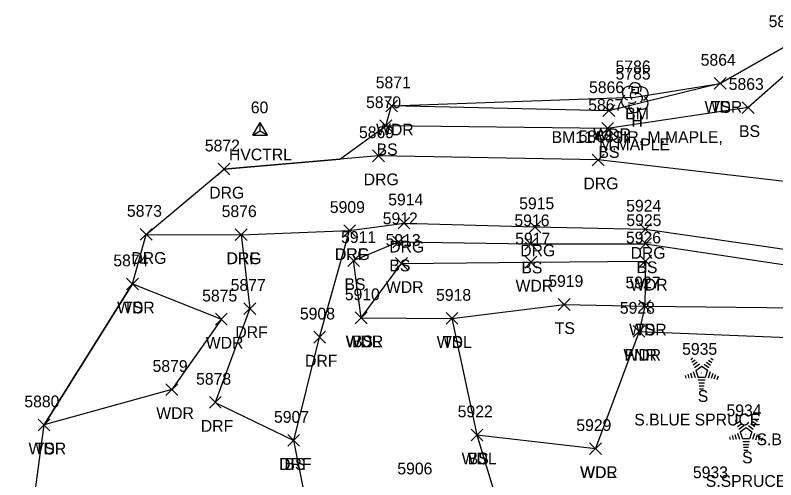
# Model space of a CAD drawing. Extents: x 1472233 to 1475777, y 540726 to 543442.
# Drawn here: x 1472262 to 1472391.2, y 541867.2 to 541946.1 of the extents above; entities that cross this region are included whole.
import ezdxf

# ---------------------------------------------------------------- set-up
doc = ezdxf.new("R2010")
doc.units = 0
for name, color, linetype in [('C_A', 7, 'Continuous'), ('C_C', 7, 'Continuous'), ('C_I', 7, 'Continuous'), ('CPBM', 7, 'Continuous'), ('CPSM', 7, 'Continuous'), ('L_A', 7, 'Continuous'), ('L_C', 7, 'Continuous'), ('L_I', 7, 'Continuous'), ('L_TIC', 7, 'Continuous'), ('LAWA', 7, 'Continuous'), ('LELB', 7, 'Continuous'), ('LFNC', 7, 'Continuous'), ('LSOGP', 7, 'Continuous'), ('LTC', 7, 'Continuous'), ('LTD', 7, 'Continuous'), ('R_A', 7, 'Continuous'), ('R_I', 7, 'Continuous'), ('R_TIC', 7, 'Continuous'), ('RDF', 7, 'Continuous'), ('RDG', 7, 'Continuous')]:
    doc.layers.add(name, color=color, linetype=linetype)

msp = doc.modelspace()

# ---------------------------------------------------------------- linework, layer by layer
at = {"layer": 'CPBM'}
for p, q in [((1472366.77, 541932.93), (1472366.77, 541933.93)), ((1472366.77, 541933.93), (1472367.77, 541933.93)), ((1472367.27, 541933.43), (1472367.27, 541933.43)), ((1472367.27, 541933.43), (1472367.27, 541933.43)), ((1472367.77, 541933.93), (1472367.77, 541932.93)), ((1472367.77, 541932.93), (1472366.77, 541932.93))]:
    msp.add_line(p, q, dxfattribs=at)
at = {"layer": 'CPSM'}
for p, q in [((1472302.37, 541925.75), (1472303.62, 541927.92)), ((1472304.87, 541925.75), (1472303.62, 541927.92)), ((1472303.62, 541926.47), (1472303.62, 541927.92)), ((1472302.37, 541925.75), (1472303.62, 541926.47)), ((1472302.37, 541925.75), (1472304.87, 541925.75)), ((1472303.62, 541926.47), (1472303.62, 541926.47)), ((1472303.62, 541926.47), (1472304.87, 541925.75))]:
    msp.add_line(p, q, dxfattribs=at)
at = {"layer": 'L_TIC'}
for points in [[(1472380.71, 541933.55), (1472382.71, 541935.55)], [(1472382.71, 541933.55), (1472380.71, 541935.55)], [(1472380.71, 541933.55), (1472382.71, 541935.55)], [(1472382.71, 541933.55), (1472380.71, 541935.55)], [(1472324.93, 541929.71), (1472326.93, 541931.71)], [(1472326.93, 541929.71), (1472324.93, 541931.71)], [(1472361.81, 541928.9), (1472363.81, 541930.9)], [(1472363.81, 541928.9), (1472361.81, 541930.9)], [(1472385.48, 541929.44), (1472387.48, 541931.44)], [(1472387.48, 541929.44), (1472385.48, 541931.44)], [(1472323.94, 541926.35), (1472325.94, 541928.35)], [(1472325.94, 541926.35), (1472323.94, 541928.35)], [(1472361.61, 541925.89), (1472363.61, 541927.89)], [(1472363.61, 541925.89), (1472361.61, 541927.89)], [(1472326.11, 541906.62), (1472328.11, 541908.62)], [(1472328.11, 541906.62), (1472326.11, 541908.62)], [(1472348.53, 541906.28), (1472350.53, 541908.28)], [(1472350.53, 541906.28), (1472348.53, 541908.28)], [(1472368.05, 541906.32), (1472370.05, 541908.32)], [(1472370.05, 541906.32), (1472368.05, 541908.32)], [(1472318.48, 541903.44), (1472320.48, 541905.44)], [(1472320.48, 541903.44), (1472318.48, 541905.44)], [(1472326.6, 541902.95), (1472328.6, 541904.95)], [(1472328.6, 541902.95), (1472326.6, 541904.95)], [(1472348.61, 541903.18), (1472350.61, 541905.18)], [(1472350.61, 541903.18), (1472348.61, 541905.18)], [(1472368.04, 541903.36), (1472370.04, 541905.36)], [(1472370.04, 541903.36), (1472368.04, 541905.36)], [(1472280.94, 541899.48), (1472282.94, 541901.48)], [(1472282.94, 541899.48), (1472280.94, 541901.48)], [(1472280.94, 541899.48), (1472282.94, 541901.48)], [(1472282.94, 541899.48), (1472280.94, 541901.48)], [(1472354.23, 541895.98), (1472356.23, 541897.98)], [(1472356.23, 541895.98), (1472354.23, 541897.98)], [(1472367.9, 541895.73), (1472369.9, 541897.73)], [(1472369.9, 541895.73), (1472367.9, 541897.73)], [(1472367.9, 541895.73), (1472369.9, 541897.73)], [(1472369.9, 541895.73), (1472367.9, 541897.73)], [(1472296.02, 541893.49), (1472298.02, 541895.49)], [(1472298.02, 541893.49), (1472296.02, 541895.49)], [(1472319.76, 541893.72), (1472321.76, 541895.72)], [(1472321.76, 541893.72), (1472319.76, 541895.72)], [(1472319.76, 541893.72), (1472321.76, 541895.72)], [(1472321.76, 541893.72), (1472319.76, 541895.72)], [(1472319.76, 541893.72), (1472321.76, 541895.72)], [(1472321.76, 541893.72), (1472319.76, 541895.72)], [(1472335.17, 541893.62), (1472337.17, 541895.62)], [(1472337.17, 541893.62), (1472335.17, 541895.62)], [(1472335.17, 541893.62), (1472337.17, 541895.62)], [(1472337.17, 541893.62), (1472335.17, 541895.62)], [(1472366.94, 541891.42), (1472368.94, 541893.42)], [(1472368.94, 541891.42), (1472366.94, 541893.42)], [(1472366.94, 541891.42), (1472368.94, 541893.42)], [(1472368.94, 541891.42), (1472366.94, 541893.42)], [(1472287.61, 541881.54), (1472289.61, 541883.54)], [(1472289.61, 541881.54), (1472287.61, 541883.54)], [(1472265.92, 541875.52), (1472267.92, 541877.52)], [(1472267.92, 541875.52), (1472265.92, 541877.52)], [(1472265.92, 541875.52), (1472267.92, 541877.52)], [(1472267.92, 541875.52), (1472265.92, 541877.52)], [(1472339.41, 541873.83), (1472341.41, 541875.83)], [(1472341.41, 541873.83), (1472339.41, 541875.83)], [(1472339.41, 541873.83), (1472341.41, 541875.83)], [(1472341.41, 541873.83), (1472339.41, 541875.83)], [(1472308.3, 541872.9), (1472310.3, 541874.9)], [(1472310.3, 541872.9), (1472308.3, 541874.9)], [(1472359.55, 541871.5), (1472361.55, 541873.5)], [(1472361.55, 541871.5), (1472359.55, 541873.5)], [(1472359.55, 541871.5), (1472361.55, 541873.5)], [(1472361.55, 541871.5), (1472359.55, 541873.5)]]:
    msp.add_lwpolyline(points, dxfattribs=at)
at = {"layer": 'LAWA'}
for points in [[(1472381.71, 541934.55), (1472362.81, 541929.9), (1472325.93, 541930.71)], [(1472320.76, 541894.72), (1472327.6, 541903.95), (1472349.61, 541904.18), (1472369.04, 541904.36), (1472368.9, 541896.73), (1472367.94, 541892.42), (1472360.55, 541872.5)], [(1472281.94, 541900.48), (1472297.02, 541894.49), (1472288.61, 541882.54), (1472266.92, 541876.52)], [(1472320.76, 541894.72), (1472336.17, 541894.62), (1472340.41, 541874.83), (1472360.55, 541872.5)]]:
    msp.add_lwpolyline(points, dxfattribs=at)
at = {"layer": 'LELB'}
for points in [[(1472393.27, 541941.1), (1472381.71, 541934.55)], [(1472396.36, 541939.17), (1472386.48, 541930.44), (1472362.61, 541926.89), (1472324.94, 541927.35)], [(1472320.76, 541894.72), (1472319.48, 541904.44), (1472327.11, 541907.62), (1472349.53, 541907.28), (1472369.05, 541907.32), (1472400.34, 541902.59), (1472412.63, 541895.66), (1472425.56, 541876.84), (1472441.12, 541840.86)], [(1472281.94, 541900.48), (1472266.92, 541876.52)], [(1472336.17, 541894.62), (1472355.23, 541896.98), (1472368.9, 541896.73), (1472400.02, 541896.36), (1472408.73, 541890.9), (1472414.63, 541871.63)], [(1472283.6, 541808.58), (1472290.39, 541830.97), (1472298.7, 541848.77), (1472310.08, 541852), (1472313.82, 541851.56), (1472309.3, 541873.9)], [(1472340.41, 541874.83), (1472344.78, 541860.43), (1472364.31, 541858.54), (1472393.01, 541845.61), (1472400.41, 541826.82), (1472401.16, 541806.06)]]:
    msp.add_lwpolyline(points, dxfattribs=at)
at = {"layer": 'LFNC'}
msp.add_lwpolyline([(1472367.94, 541892.42), (1472397.42, 541891.24), (1472408.73, 541890.9), (1472418.35, 541874.05), (1472429.29, 541846.34), (1472434.3, 541834.91), (1472432.16, 541828.28)], dxfattribs=at)
at = {"layer": 'LSOGP'}
msp.add_lwpolyline([(1472313.53, 541780.33), (1472308.58, 541803.57), (1472307.76, 541802.6), (1472300.01, 541804.6), (1472283.6, 541808.58), (1472268.24, 541812.15), (1472267.36, 541823.78), (1472262.02, 541839.94), (1472266.92, 541876.52), (1472281.94, 541900.48), (1472284.25, 541908.89), (1472297.47, 541919.99), (1472304.03, 541920.55), (1472310.58, 541921.11), (1472317.14, 541921.67), (1472324.94, 541927.35), (1472325.93, 541930.71), (1472367.22, 541932.19), (1472381.71, 541934.55), (1472393.27, 541941.1)], dxfattribs=at)
at = {"layer": 'LTC'}
for p, q in [((1472376.72, 541887.65), (1472377.07, 541887.91)), ((1472376.93, 541887.19), (1472377.45, 541887.57)), ((1472377.13, 541886.72), (1472377.84, 541887.23)), ((1472377.34, 541886.26), (1472378.22, 541886.89)), ((1472379, 541886.85), (1472379.81, 541886.26)), ((1472379.37, 541887.2), (1472380.05, 541886.7)), ((1472379.74, 541887.55), (1472380.29, 541887.15)), ((1472380.11, 541887.89), (1472380.53, 541887.59)), ((1472377.11, 541885.58), (1472377.45, 541884.56)), ((1472377.57, 541885.8), (1472378.58, 541886.54)), ((1472377.57, 541885.8), (1472377.96, 541884.61)), ((1472378.58, 541886.54), (1472379.58, 541885.81)), ((1472379.58, 541885.81), (1472379.19, 541884.61)), ((1472380.02, 541885.54), (1472379.68, 541884.5)), ((1472375.75, 541884.93), (1472375.9, 541884.46)), ((1472376.2, 541885.15), (1472376.42, 541884.5)), ((1472376.66, 541885.37), (1472376.93, 541884.53)), ((1472379.19, 541884.61), (1472377.96, 541884.61)), ((1472380.46, 541885.29), (1472380.17, 541884.4)), ((1472380.9, 541885.04), (1472380.67, 541884.31)), ((1472381.35, 541884.79), (1472381.16, 541884.21)), ((1472379.15, 541884.11), (1472378, 541884.11)), ((1472379.06, 541883.61), (1472378.08, 541883.61)), ((1472378.98, 541883.11), (1472378.15, 541883.11)), ((1472378.9, 541882.61), (1472378.22, 541882.61)), ((1472384.25, 541877.22), (1472384.6, 541877.47)), ((1472384.46, 541876.75), (1472384.99, 541877.14)), ((1472384.67, 541876.29), (1472385.37, 541876.8)), ((1472386.9, 541876.76), (1472387.58, 541876.27)), ((1472387.28, 541877.11), (1472387.82, 541876.71)), ((1472387.65, 541877.46), (1472388.07, 541877.15)), ((1472384.88, 541875.82), (1472385.76, 541876.46)), ((1472385.1, 541875.37), (1472386.11, 541876.1)), ((1472385.1, 541875.37), (1472385.49, 541874.17)), ((1472386.11, 541876.1), (1472387.11, 541875.37)), ((1472386.53, 541876.41), (1472387.34, 541875.82)), ((1472387.11, 541875.37), (1472386.72, 541874.17)), ((1472383.28, 541874.5), (1472383.43, 541874.03)), ((1472383.74, 541874.71), (1472383.95, 541874.06)), ((1472384.19, 541874.93), (1472384.46, 541874.09)), ((1472384.65, 541875.15), (1472384.98, 541874.13)), ((1472386.72, 541874.17), (1472385.49, 541874.17)), ((1472387.55, 541875.1), (1472387.21, 541874.06)), ((1472387.99, 541874.85), (1472387.7, 541873.97)), ((1472388.44, 541874.6), (1472388.2, 541873.87)), ((1472388.88, 541874.35), (1472388.69, 541873.78)), ((1472386.68, 541873.67), (1472385.54, 541873.67)), ((1472386.6, 541873.17), (1472385.61, 541873.17)), ((1472386.51, 541872.67), (1472385.68, 541872.67)), ((1472386.43, 541872.17), (1472385.75, 541872.17))]:
    msp.add_line(p, q, dxfattribs=at)
at = {"layer": 'LTD'}
msp.add_line((1472367.22, 541932.19), (1472367.22, 541932.19), dxfattribs=at)
msp.add_line((1472367.22, 541932.19), (1472367.22, 541932.19), dxfattribs=at)
msp.add_arc((1472367.26, 541933.62), 1.05, 335.5272, 180.9563, dxfattribs=at)
for centre, major_axis, ratio, start_param, end_param in [((1472366.42, 541932.86), (1.21, -0.51), 0.895232, 1.570796, 4.712389), ((1472367.01, 541932.65), (-0.208, -0.792), 0.645439, 3.141593, 6.283185), ((1472368.26, 541932.77), (-1.14, -0.48), 0.949671, 1.570796, 4.712389), ((1472366.13, 541931.48), (0.58, -1.04), 0.959034, 3.141593, 6.283185), ((1472367.72, 541932.02), (-0.5, 0.667), 0.989748, 3.141593, 6.283185), ((1472368.22, 541931.36), (-1.09, 0.79), 0.841452, 1.570796, 4.712389), ((1472367.22, 541930.69), (0.26, 1.06), 0.942809, 1.570796, 4.712389), ((1472366.76, 541931.44), (-0.625, -0.083), 0.423636, 0, 3.141593)]:
    msp.add_ellipse(centre, major_axis=major_axis, ratio=ratio, start_param=start_param, end_param=end_param, dxfattribs=at)
at = {"layer": 'R_TIC'}
for points in [[(1472322.7, 541921.24), (1472324.7, 541923.24)], [(1472324.7, 541921.24), (1472322.7, 541923.24)], [(1472360.01, 541920.55), (1472362.01, 541922.55)], [(1472362.01, 541920.55), (1472360.01, 541922.55)], [(1472296.47, 541918.99), (1472298.47, 541920.99)], [(1472298.47, 541918.99), (1472296.47, 541920.99)], [(1472327.04, 541909.82), (1472329.04, 541911.82)], [(1472329.04, 541909.82), (1472327.04, 541911.82)], [(1472317.79, 541908.54), (1472319.79, 541910.54)], [(1472319.79, 541908.54), (1472317.79, 541910.54)], [(1472317.79, 541908.54), (1472319.79, 541910.54)], [(1472319.79, 541908.54), (1472317.79, 541910.54)], [(1472349.28, 541909.17), (1472351.28, 541911.17)], [(1472351.28, 541909.17), (1472349.28, 541911.17)], [(1472368.02, 541908.76), (1472370.02, 541910.76)], [(1472370.02, 541908.76), (1472368.02, 541910.76)], [(1472283.25, 541907.89), (1472285.25, 541909.89)], [(1472285.25, 541907.89), (1472283.25, 541909.89)], [(1472299.38, 541907.84), (1472301.38, 541909.84)], [(1472301.38, 541907.84), (1472299.38, 541909.84)], [(1472299.38, 541907.84), (1472301.38, 541909.84)], [(1472301.38, 541907.84), (1472299.38, 541909.84)], [(1472300.86, 541895.3), (1472302.86, 541897.3)], [(1472302.86, 541895.3), (1472300.86, 541897.3)], [(1472312.7, 541890.44), (1472314.7, 541892.44)], [(1472314.7, 541890.44), (1472312.7, 541892.44)], [(1472294.99, 541879.36), (1472296.99, 541881.36)], [(1472296.99, 541879.36), (1472294.99, 541881.36)], [(1472308.3, 541872.9), (1472310.3, 541874.9)], [(1472310.3, 541872.9), (1472308.3, 541874.9)]]:
    msp.add_lwpolyline(points, dxfattribs=at)
at = {"layer": 'RDF'}
msp.add_lwpolyline([(1472300.38, 541908.84), (1472301.86, 541896.3), (1472295.99, 541880.36), (1472309.3, 541873.9), (1472313.7, 541891.44), (1472318.79, 541909.54)], dxfattribs=at)
at = {"layer": 'RDG'}
for points in [[(1472417.04, 541924.07), (1472412.17, 541918.8), (1472398.55, 541917.2), (1472361.01, 541921.55), (1472323.7, 541922.24), (1472297.47, 541919.99)], [(1472284.25, 541908.89), (1472300.38, 541908.84), (1472318.79, 541909.54), (1472328.04, 541910.82), (1472350.28, 541910.17), (1472369.02, 541909.76), (1472411.16, 541903.71), (1472423.64, 541895.51), (1472429.27, 541890.41)]]:
    msp.add_lwpolyline(points, dxfattribs=at)

# ---------------------------------------------------------------- texts
at = {"layer": 'C_A'}
for s, p in [('BM', (1472365.59, 541928.43)), ('HVCTRL', (1472298.31, 541921.47))]:
    msp.add_text(s, height=2, dxfattribs=at).set_placement(p)
at = {"layer": 'C_C'}
msp.add_text('BM11A=SIR, M.MAPLE,', height=2, dxfattribs=at).set_placement((1472353.1, 541924.43))
at = {"layer": 'C_I'}
for s, p in [('5786', (1472363.96, 541936.43)), ('60', (1472302.02, 541929.47))]:
    msp.add_text(s, height=2, dxfattribs=at).set_placement(p)
at = {"layer": 'L_A'}
for s, p in [('WDR', (1472379.08, 541929.55)), ('TS', (1472380.12, 541929.55)), ('H', (1472366.65, 541927.19)), ('WDR', (1472323.29, 541925.71)), ('WDR', (1472360.17, 541924.9)), ('BS', (1472384.92, 541925.44)), ('BS', (1472323.38, 541922.35)), ('BS', (1472361.06, 541921.89)), ('BS', (1472325.55, 541902.62)), ('BS', (1472347.97, 541902.28)), ('BS', (1472367.5, 541902.32)), ('BS', (1472317.92, 541899.44)), ('WDR', (1472346.98, 541899.18)), ('WDR', (1472366.4, 541899.36)), ('WDR', (1472324.96, 541898.95)), ('WDR', (1472279.31, 541895.48)), ('TS', (1472280.35, 541895.48)), ('TS', (1472353.64, 541891.98)), ('WDR', (1472366.26, 541891.73)), ('TS', (1472367.31, 541891.73)), ('WDR', (1472294.38, 541889.49)), ('WDR', (1472318.12, 541889.72)), ('WDL', (1472318.18, 541889.72)), ('BS', (1472319.2, 541889.72)), ('WDL', (1472333.59, 541889.62)), ('TS', (1472334.58, 541889.62)), ('WDR', (1472365.3, 541887.42)), ('FNR', (1472365.47, 541887.42)), ('S', (1472377.91, 541880.44)), ('WDR', (1472285.97, 541877.54)), ('WDR', (1472264.28, 541871.52)), ('TS', (1472265.33, 541871.52)), ('WDL', (1472337.82, 541869.83)), ('BS', (1472338.85, 541869.83)), ('S', (1472385.44, 541870.01)), ('BS', (1472307.74, 541868.9)), ('WDR', (1472357.92, 541867.5)), ('WDL', (1472357.97, 541867.5))]:
    msp.add_text(s, height=2, dxfattribs=at).set_placement(p)
at = {"layer": 'L_C'}
for s, p in [('M.MAPLE', (1472361.15, 541923.19)), ('S.BLUE SPRUCE', (1472367.13, 541876.44)), ('S.BLUE SPRUCE', (1472387.89, 541873.09)), ('S.SPRUCE', (1472379.27, 541866.01))]:
    msp.add_text(s, height=2, dxfattribs=at).set_placement(p)
at = {"layer": 'L_I'}
for s, p in [('5856', (1472389.95, 541944.1)), ('5864', (1472378.41, 541937.55)), ('5864', (1472378.41, 541937.55)), ('5785', (1472363.96, 541935.19)), ('5871', (1472323.23, 541933.71)), ('5866', (1472359.45, 541932.9)), ('5863', (1472383.17, 541933.44)), ('5870', (1472321.59, 541930.35)), ('5867', (1472359.31, 541929.89)), ('5912', (1472324.42, 541910.62)), ('5916', (1472346.78, 541910.28)), ('5925', (1472365.79, 541910.32)), ('5911', (1472317.35, 541907.44)), ('5913', (1472324.91, 541906.95)), ('5917', (1472346.92, 541907.18)), ('5926', (1472365.72, 541907.36)), ('5874', (1472278.68, 541903.48)), ('5874', (1472278.68, 541903.48)), ('5919', (1472352.53, 541899.98)), ('5927', (1472365.64, 541899.73)), ('5927', (1472365.64, 541899.73)), ('5910', (1472317.98, 541897.72)), ('5910', (1472317.98, 541897.72)), ('5910', (1472317.98, 541897.72)), ('5875', (1472293.76, 541897.49)), ('5918', (1472333.48, 541897.62)), ('5918', (1472333.48, 541897.62)), ('5928', (1472364.68, 541895.42)), ('5928', (1472364.68, 541895.42)), ('5935', (1472375.26, 541888.44)), ('5879', (1472285.34, 541885.54)), ('5880', (1472263.57, 541879.52)), ('5880', (1472263.57, 541879.52)), ('5922', (1472337.15, 541877.83)), ('5922', (1472337.15, 541877.83)), ('5934', (1472382.79, 541878.01)), ('5907', (1472305.96, 541876.9)), ('5929', (1472357.29, 541875.5)), ('5929', (1472357.29, 541875.5)), ('5906', (1472326.9, 541868.13)), ('5933', (1472377.09, 541867.48))]:
    msp.add_text(s, height=2, dxfattribs=at).set_placement(p)
at = {"layer": 'LTC'}
for p in [(1472378.46, 541885.55), (1472386, 541875.11)]:
    msp.add_text('.', height=1.04, rotation=270, dxfattribs=at).set_placement(p)
at = {"layer": 'R_A'}
for s, p in [('DRG', (1472321.19, 541917.24)), ('DRG', (1472358.5, 541916.55)), ('DRG', (1472294.96, 541914.99)), ('DRG', (1472325.53, 541905.82)), ('DRG', (1472316.27, 541904.54)), ('DRF', (1472316.32, 541904.54)), ('DRG', (1472347.77, 541905.17)), ('DRG', (1472366.5, 541904.76)), ('DRG', (1472281.74, 541903.89)), ('DRG', (1472297.87, 541903.84)), ('DRF', (1472297.92, 541903.84)), ('DRF', (1472299.39, 541891.3)), ('DRF', (1472311.23, 541886.44)), ('DRF', (1472293.53, 541875.36)), ('DRF', (1472306.83, 541868.9))]:
    msp.add_text(s, height=2, dxfattribs=at).set_placement(p)
at = {"layer": 'R_I'}
for s, p in [('5869', (1472320.39, 541925.24)), ('5868', (1472357.7, 541924.55)), ('5872', (1472294.21, 541922.99)), ('5914', (1472325.35, 541913.82)), ('5909', (1472315.44, 541912.54)), ('5909', (1472315.44, 541912.54)), ('5915', (1472347.59, 541913.17)), ('5924', (1472365.76, 541912.76)), ('5873', (1472280.99, 541911.89)), ('5876', (1472297.07, 541911.84)), ('5876', (1472297.07, 541911.84)), ('5877', (1472298.6, 541899.3)), ('5908', (1472310.36, 541894.44)), ('5878', (1472292.73, 541883.36)), ('5907', (1472305.96, 541876.9))]:
    msp.add_text(s, height=2, dxfattribs=at).set_placement(p)

doc.saveas('drawing.dxf')
